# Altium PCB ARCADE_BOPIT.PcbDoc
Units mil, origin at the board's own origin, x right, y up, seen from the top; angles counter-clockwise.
Board outline 5835 x 3835 mil, 2 copper layers (Top Layer, Bottom Layer); 35 components, 24 nets, 112 pads, 0 vias.
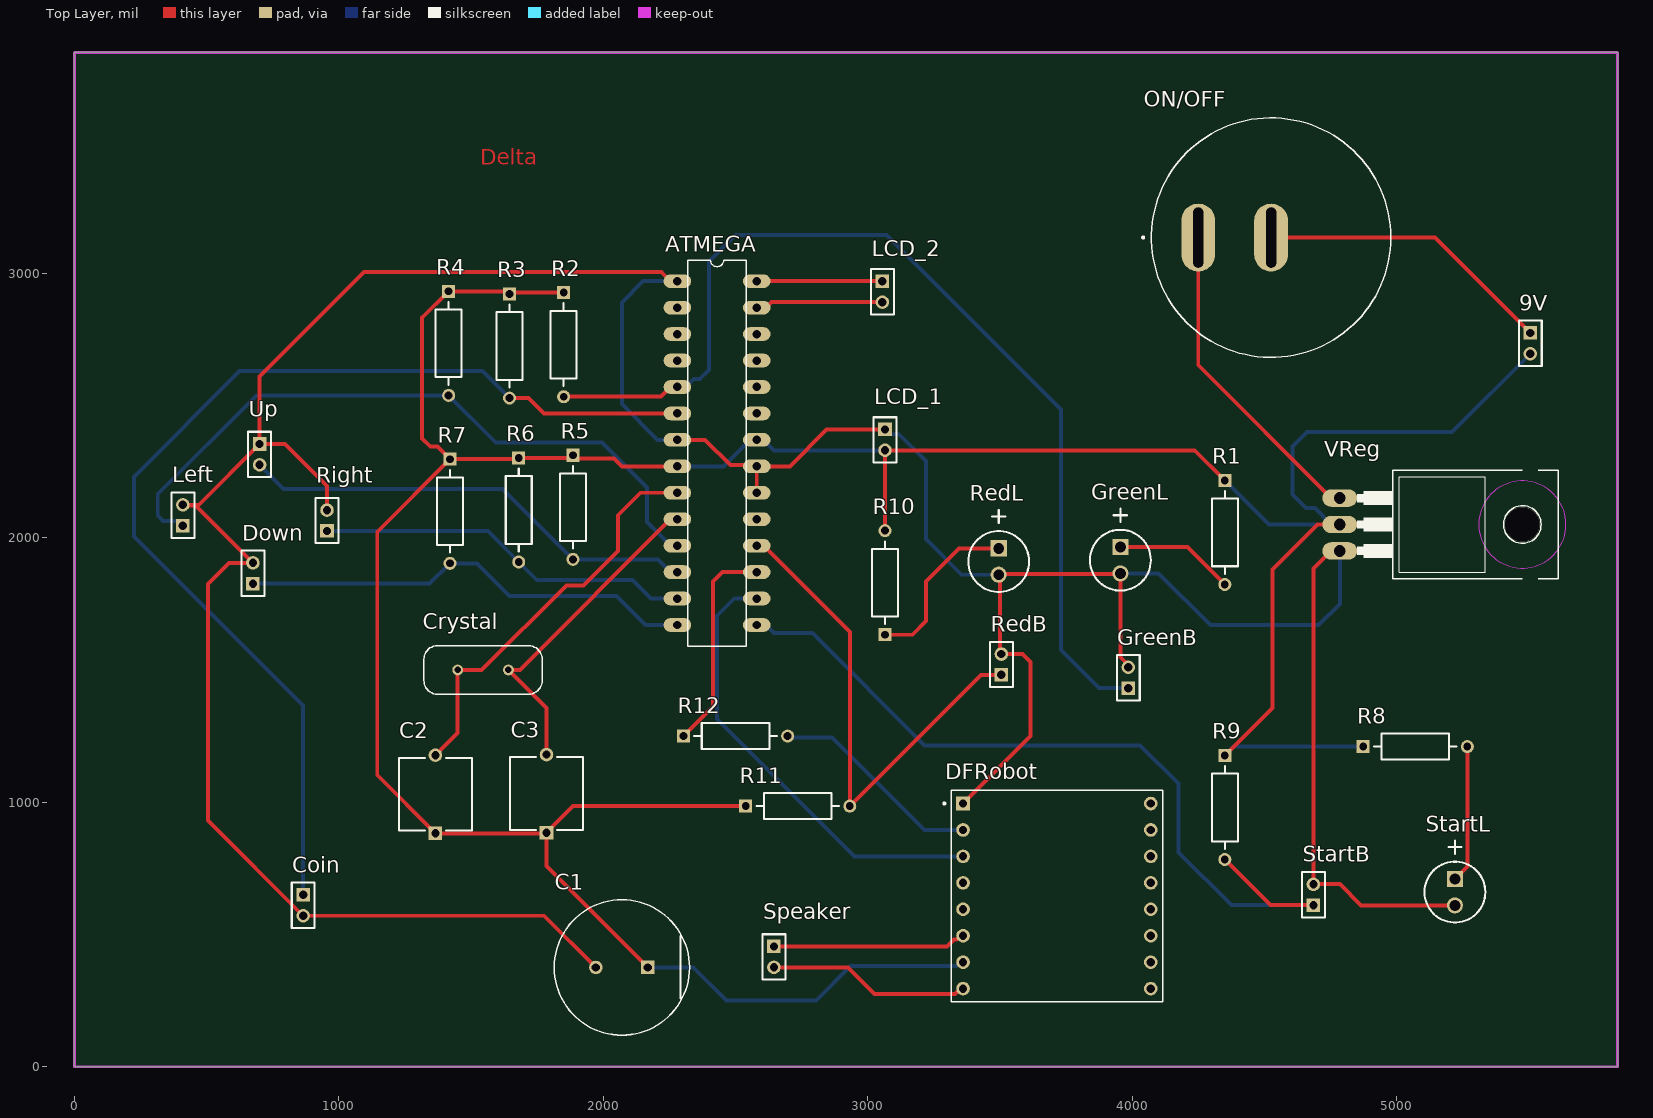
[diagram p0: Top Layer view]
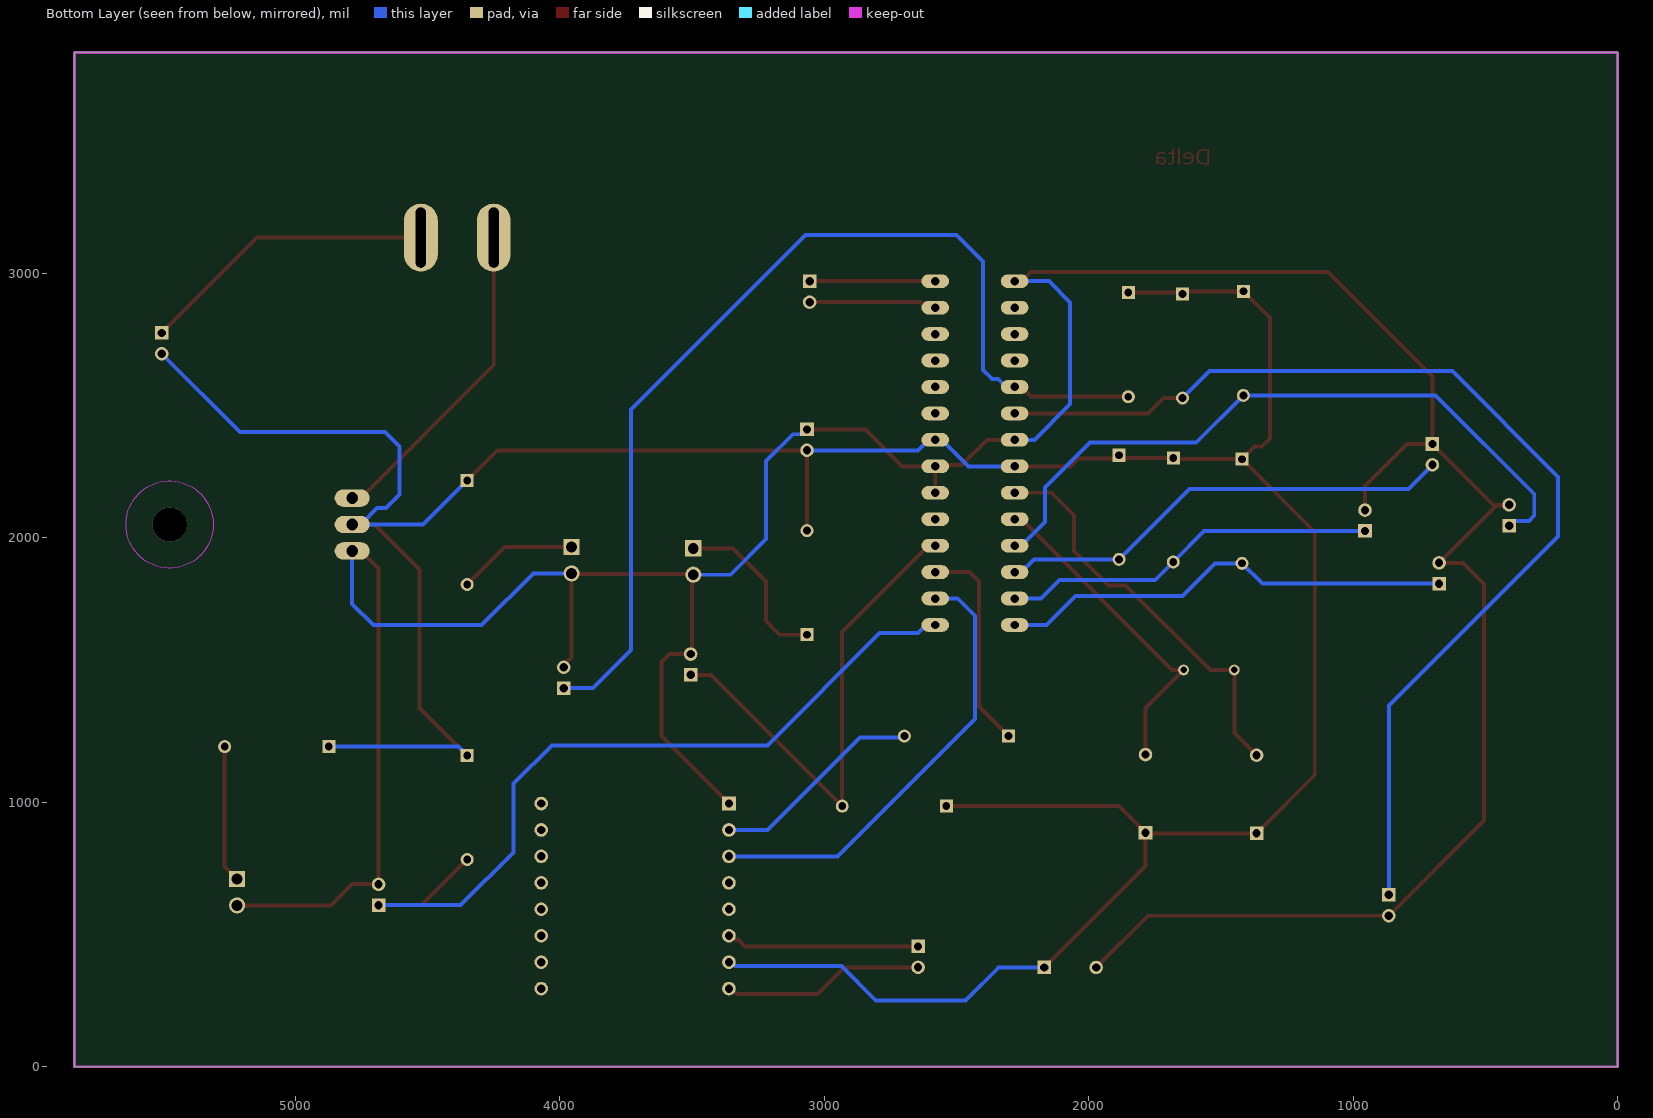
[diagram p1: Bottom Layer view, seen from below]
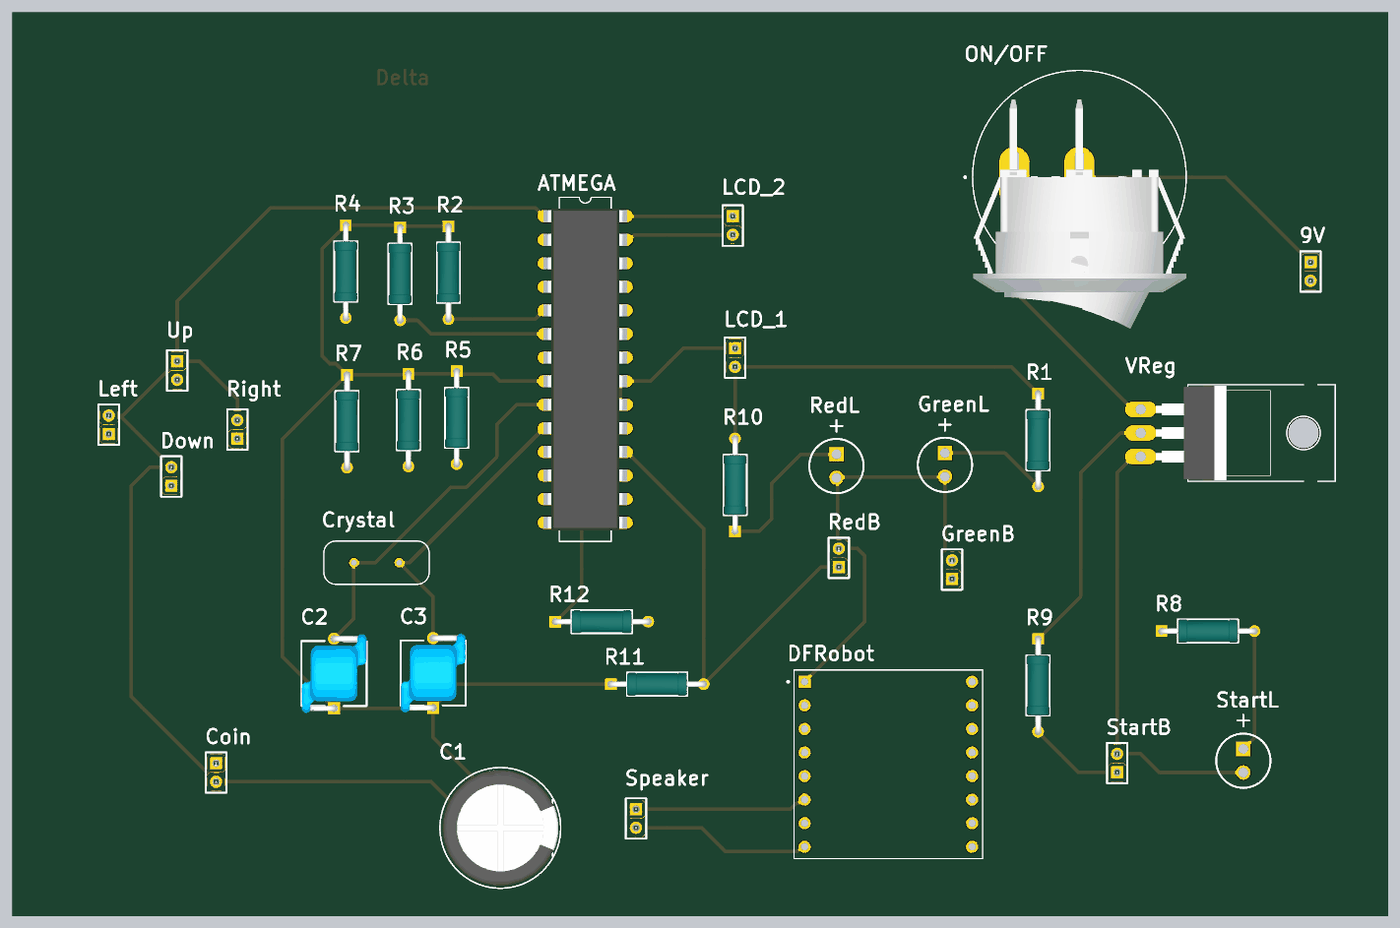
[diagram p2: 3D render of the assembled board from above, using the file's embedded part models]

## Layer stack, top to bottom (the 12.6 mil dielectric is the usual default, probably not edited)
Top Solder: solder mask 0.4, Solder Resist, Dk 3.5
Top Layer: signal copper 1.4
Dielectric 1: dielectric 12.6, FR-4, Dk 4.8
Bottom Layer: signal copper 1.4
Bottom Solder: solder mask 0.4, Solder Resist, Dk 3.5

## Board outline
0,0 5835,0 5835,3835 0,3835

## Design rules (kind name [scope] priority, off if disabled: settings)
BoardOutlineClearance [All] p1: gap=7.87 ignorepadtopadclearanceinfootprint=FALSE except(15.75: Arc-SplitBarrior Arc-SplitContinuation Track-SplitBarrior Track-SplitContinuation SMDPad-SplitBarrior SMDPad-SplitContinuation THPad-SplitBarrior THPad-SplitContinuation Via-SplitBarrior Via-SplitContinuation Fill-SplitBarrior Fill-SplitContinuation Poly-SplitBarrior Poly-SplitContinuation Region-SplitBarrior Region-SplitContinuation Text-SplitBarrior Text-SplitContinuation)
Clearance "Clearance Bottom Layer" [OnLayer('Bottom Layer')] p1: gap=8 ignorepadtopadclearanceinfootprint=TRUE except(10: Arc-Text Track-Text SMDPad-Text THPad-Text Via-Text Fill-Text Poly-Text Region-Text Text-Text)
Clearance "Clearance Top Layer" [OnLayer('Top Layer')] p2: gap=8 ignorepadtopadclearanceinfootprint=TRUE except(10: Arc-Text Track-Text SMDPad-Text THPad-Text Via-Text Fill-Text Poly-Text Region-Text Text-Text)
Clearance [All] p3: gap=7.87 ignorepadtopadclearanceinfootprint=FALSE except(3.5: Arc-Arc Arc-Track Arc-SMDPad Track-Track Track-SMDPad SMDPad-SMDPad; 5: Arc-Via Track-Via SMDPad-Via THPad-Via Via-Via; 10: Arc-Text Track-Text SMDPad-Text THPad-Text Via-Text Fill-Text Poly-Text Region-Text Text-Text)
HoleSize [All] p1: absolutevalues=TRUE maxlimit=248.03 minlimit=7.87 maxpercent=80.000 minpercent=20.000
MinimumAnnularRing [All] p1: minimumring=3
MinimumSolderMaskSliver [All] p1: minsoldermaskwidth=3.94
PolygonConnect PolygonConnect_1 [All] p1: thpad.connectstyle=Relief thpad.reliefconductorwidth=20 thpad.reliefentries=4 thpad.polygonreliefangle="90 Angle" thpad.airgapwidth=10 smdpad.connectstyle=Relief smdpad.reliefconductorwidth=20 smdpad.reliefentries=4 smdpad.polygonreliefangle="90 Angle" smdpad.airgapwidth=10 via.connectstyle=Direct via.reliefconductorwidth=20 via.reliefentries=4 via.polygonreliefangle="90 Angle" via.airgapwidth=10
RoutingCorners [All] p1: cornerstyle=Round minsetback=100 maxsetback=100
RoutingVias [All] p1: holewidth=19.68 width=39.37 viastyle="Through Hole" minholewidth=7.87 minwidth=17.72 maxholewidth=39.37 maxwidth=78.74
SilkToSilkClearance [All] p1: silktosilkclearance=3.94
SilkToSolderMaskClearance [IsPad] p1: minsilkscreentomaskgap=3.94 clearancetoexposedcopper=TRUE
SolderMaskExpansion [All] p1: expansion=4 istentingtop=FALSE
Width [All] p1: maxlimit=100 minlimit=3.5 preferedwidth=15
25 further rules are at their usual default settings.

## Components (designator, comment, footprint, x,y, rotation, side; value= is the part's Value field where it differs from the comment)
9V "9V" FP-M22-2510205-MFG 5505,2735 r270 top
ATMEGA "ATMEGA328P-PN" DIL28 2430,2320 r0 top
C1 "0.33uF" FP-RAD-TH-D_12_5_0_5-L_20-MFG 2070,375 r180 top
C2 "22pF" FP-DE6_D7_T7_F7_5_d0_6-0-MFG 1365,1030 r90 top
C3 "22pF" FP-DE6_D7_T7_F7_5_d0_6-0-MFG 1785,1032.36 r90 top
Coin "Coin" FP-M22-2510205-MFG 865,610 r270 top
Crystal "Crystal" XTAL_ECS-160-20-4X 1545,1500 r180 top
DFRobot "DFR0299" MODULE_DFR0299 3715,645 r0 top
Down "Down" FP-M22-2510205-MFG 675,1865.63 r90 top
GreenB "Green Button" FP-M22-2510205-MFG 3985,1470.63 r90 top
GreenL "GreenLED" AVAG-HLMP-3301-2 3955,1965 r270 top
LCD_1 "LCD_1" FP-M22-2510205-MFG 3065,2370 r270 top
LCD_2 "LCD_2" FP-M22-2510205-MFG 3055,2930 r270 top
Left "Left" FP-M22-2510205-MFG 410,2085 r90 top
ON/OFF "On/Off Switch" E-SWITCH_RR511D1121 4525,3135 r0 top
R1 "1k" FP-MRS25-MFG 4350,2020 r270 top
R2 "1k" FP-MRS25-MFG 1850,2730 r270 top
R3 "1k" FP-MRS25-MFG 1645,2725 r270 top
R4 "1k" FP-MRS25-MFG 1415,2735 r270 top
R5 "1k" FP-MRS25-MFG 1885,2115 r270 top
R6 "1k" FP-MRS25-MFG 1680,2105 r270 top
R7 "1k" FP-MRS25-MFG 1420,2100 r270 top
R8 "1k" FP-MRS25-MFG 5070,1210 r0 top
R9 "1k" FP-MRS25-MFG 4350,980 r270 top
R10 "1k" FP-MRS25-MFG 3065,1830 r90 top
R11 "1k" FP-MRS25-MFG 2735,985 r0 top
R12 "1k" FP-MRS25-MFG 2500,1250 r0 top
RedB "RedB" FP-M22-2510205-MFG 3505,1520.63 r90 top
RedL "RedL" AVAG-HLMP-3301-2 3495,1960 r270 top
Right "Right" FP-M22-2510205-MFG 955,2065 r90 top
Speaker "Speaker" FP-M22-2510205-MFG 2645,415 r270 top
StartB "StartB" FP-M22-2510205-MFG 4685,650 r90 top
StartL "StartL" AVAG-HLMP-3301-2 5220,710 r270 top
Up "Up" FP-M22-2510205-MFG 700,2315 r270 top
VReg "Voltage Regulator" TO220 5035,2050 r270 top

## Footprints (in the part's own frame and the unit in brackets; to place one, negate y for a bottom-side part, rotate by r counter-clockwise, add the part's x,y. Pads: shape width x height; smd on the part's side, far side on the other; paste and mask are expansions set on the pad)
AVAG-HLMP-3301-2 [mm] "THD, 2-Leads, Body Dia 5.85mm"
  rect 1.55x1.55 hole 1.05: 1(0,0)
  round 1.55 hole 1.05: 2(2.54,0)
  silkscreen extent -3.68,-2.92 4.19,2.92
DIL28 [mil]
  oval 104x52 hole 32: 1(-150,650) 2(-150,550) 3(-150,450) 4(-150,350) 5(-150,250) 6(-150,150) 7(-150,50) 8(-150,-50) 9(-150,-150) 10(-150,-250) 11(-150,-350) 12(-150,-450) 13(-150,-550) 14(-150,-650) 15(150,-650) 16(150,-550) 17(150,-450) 18(150,-350) 19(150,-250) 20(150,-150) 21(150,-50) 22(150,50) 23(150,150) 24(150,250) 25(150,350) 26(150,450) 27(150,550) 28(150,650)
  silkscreen extent -110,-730 110,730, body extent -200,-682 200,682, height 180
E-SWITCH_RR511D1121 [mm]
  oval 3.26x6.52 hole 0.98 slot 5.78 at 90 deg: 1(-7,0) 2(0,0)
  silkscreen extent -12.4,-11.5 11.5,11.5, body extent -11.5,-16.33 11.5,8.4, height 11.5
FP-DE6_D7_T7_F7_5_d0_6-0-MFG [mm]
  rect 1.3x1.3 hole 0.8 paste-1000 mask+0: 1(-3.75,0)
  round 1.3 hole 0.8 paste-1000 mask+0: 2(3.75,0)
  silkscreen extent -3.5,-3.5 3.5,3.5, body extent -4.5,-3.6 4.5,3.6, height 0.25
FP-M22-2510205-MFG [mm]
  rect 1.3x1.3 hole 0.8 paste-1000 mask+0: 1(-1,0)
  round 1.3 hole 0.8 paste-1000 mask+0: 2(1,0)
  silkscreen extent -2.17,-1.1 2.17,1.1, body extent -2.27,-1.2 2.27,1.2, height 0.25
FP-MRS25-MFG [mm]
  rect 1.25x1.25 hole 0.75 paste-1000 mask+0: 1(-5,0)
  round 1.25 hole 0.75 paste-1000 mask+0: 2(5,0)
  silkscreen extent -3.98,-1.25 3.98,1.25, body extent -5.72,-1.35 5.72,1.35, height 0.25
FP-RAD-TH-D_12_5_0_5-L_20-MFG [mm]
  rect 1.3x1.3 hole 0.8 paste-1000 mask+0: 1(-2.5,0)
  round 1.3 hole 0.8 paste-1000 mask+0: 2(2.5,0)
  silkscreen extent -6.5,-6.5 6.5,6.5, body extent -6.6,-6.6 6.6,6.6, height 0.25
MODULE_DFR0299 [mil]
  rect 51.5x51.5 hole 31.5: 1(-355,350)
  round 51.5 hole 31.5: 2(-355,250) 3(-355,150) 4(-355,50) 5(-355,-50) 6(-355,-150) 7(-355,-250) 8(-355,-350) 9(355,-350) 10(355,-250) 11(355,-150) 12(355,-50) 13(355,50) 14(355,150) 15(355,250) 16(355,350)
  silkscreen extent -429,-400 400,400
TO220 [mil]
  oval 66x132 hole 44: 1(-100,-250) 2(0,-250) 3(100,-250)
  round 130 hole 130 unplated: ""(0,440)
  Keep-Out Layer circle w0: c0,440 r165
  Keep-Out Layer circle w0: c0,440 r165
  silkscreen extent -205,-185 205,575, body extent -200,-68 200,113, height 1155
XTAL_ECS-160-20-4X [mm]
  round 1.03 hole 0.63: 1(-2.44,0) 2(2.44,0)
  silkscreen extent -5.68,-2.33 5.68,2.33

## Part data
9V Coin Down GreenB LCD_1 LCD_2 Left RedB Right Speaker StartB Up: library part CMP-15831-000005-1, "CONN HEADER VERT 2POS 2MM", Current Rating=2A, Manufacturer=Harwin, Manufacturer Part Number=M22-2510205, Package=0, Temperature="-40°C to +105°C", Temperature Range High=+105°C, Temperature Range Low=-40°C
ATMEGA: "AVR AVRÂ® ATmega Microcontroller IC 8-Bit 20MHz 32KB (16K x 16) FLASH 28-PDIP", Package="PDIP-28 Microchip"
C1: library part CMP-05427-000342-1, "Aluminum Electrolytic Capacitors (Radial Lead Type) AEC-Q200 Qualified 2200uF ±20% 16V", Capacitance=2.2mF, Case/Package=Radial, Dielectric Material=Aluminium, Max Operating Temperature=105°C, Min Operating Temperature=-55°C, Package Quantity=200, Ripple Current=1.89A, Tolerance=20%, Voltage=16V
C2 C3: library part CMP-06035-062244-1, "CAP CER 1000PF 300VAC RADIAL", Capacitance=1nF, Case/Package=Radial, Max Operating Temperature=125°C, Min Operating Temperature=-25°C, Package Quantity=700, Ratings=AEC-Q200, Resistor Type=Ceramic, Tolerance=20%, Voltage Rating (AC)=300V
Crystal: library part ECS-160-S-4, "16MHz Â±30ppm Crystal Series 40 Ohms HC-49/US", Package="HC49/US ECS International"
DFRobot: "Dfplayer - a Mini Mp3 Player", Package=None
GreenL RedL StartL: library part CMP-2000-06411-1, "T-1 3/4 (5 mm) Diffused LED Lamp, 1.9 V, -40 to 100 degC, 2-Pin THD, RoHS, Bulk", Emitting Color=Red, Forward Current=25mA, Forward Voltage=2.4V, Manufacturer=Avago, Operating Temp Range=-40Cto100C, Operating Temperature Classification=Industrial, Package Description="2-Pin Through Hole LED, Dia 5.85 mm", Package Reference=HLMP-3301, Package Type=T-13/4, Power Dissipation=85W, Reverse Voltage=5V, Test Current (It)=10mA
ON/OFF: library part RR511D1121, "Rocker Switch, RR5 Series, SPST,OFF-ON,Blk Rocker,I/O Legend, 20A, 125VAC, QC", Package=None
R1 R2 R3 R4 R5 R6 R7 R8 R9 R10 R11 R12: library part CMP-02408-000051-1, "RES 1K OHM 0.6W 1% AXIAL", Case/Package=Axial, Max Operating Temperature=155°C, Max Power Dissipation=600mW, Min Operating Temperature=-55°C, Package Quantity=5000, Resistance=1kR, Resistance Tolerance=1%, Resistor Type="Metal Film", Temperature Coefficient=50ppm/°C, Voltage Rating=350V
VReg: library part LM7805, "Linear Voltage Regulator IC Positive Fixed 1 Output 1.5A DDPAK/TO-263-3", Package=None

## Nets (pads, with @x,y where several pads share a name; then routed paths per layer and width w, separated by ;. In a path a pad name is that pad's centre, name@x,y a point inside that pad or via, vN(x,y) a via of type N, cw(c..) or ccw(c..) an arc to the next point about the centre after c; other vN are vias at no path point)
GND: 9V.2 ATMEGA.8 ATMEGA.22 C1.1 C2.1 C3.1 DFRobot.7 LCD_1.2 R1.1 R2.1 R3.1 R4.1 R5.1 R6.1 R7.1 R8.1 R9.1 R10.2 R11.1 VReg.2 | length 12879.7
  Top Layer w15: R2.1 1650,2926.85 R3.1 1635,2931.85 R4.1 1315,2831.85 1315,2375 1345.52,2344.48 1372.37,2344.48 R7.1 ; C1.1 1785,758.43 C3.1 ; ATMEGA.8 2070,2270 2040,2300 1896.85,2300 R5.1 1875,2301.85 R6.1 1675,2296.85 R7.1 ; R11.1 1885.28,985 C3.1 ; R10.2 LCD_1.2 4236.22,2330.63 R1.1 ; R9.1 4530,1356.85 4530,1880 4700,2050 VReg.2 ; R7.1 1145,2021.85 1145,1102.36 C2.1 1782.64,882.36 C3.1
  Bottom Layer w15: C1.1 2340,375 2460.01,254.99 2465,250 2805,250 2935,380 3335,380 ; ATMEGA.8 2454,2270 2554,2370 ATMEGA.22 2606,2370 2645.37,2330.63 LCD_1.2 ; R9.1 4383.15,1210 R8.1 ; R1.1 4516.85,2050 VReg.2@4752,2050 ; VReg.2 VReg.2@4752,2050 ; 9V.2 5209.37,2400 4660,2400 4605,2345 4605,2163.79 4657.01,2111.77 4690.23,2111.77 VReg.2@4752,2050
Net9V_1: 9V.1 ON/OFF.2 | length 1129.4
  Top Layer w15: ON/OFF.2 5144.37,3135 9V.1
NetATMEGA_5: ATMEGA.5 GreenB.1 R2.2 | length 3871.5
  Top Layer w15: R2.2 2217.15,2533.15 2254,2570 ATMEGA.5
  Bottom Layer w15: ATMEGA.5 2312.51,2570 2343.55,2601.04 2366.04,2601.04 2400,2635 2400,3045 2500,3145 3070,3145 3730,2485 3730,1575 3873.74,1431.26 GreenB.1
NetATMEGA_6: ATMEGA.6 Coin.1 R3.2 | length 4132.7
  Top Layer w15: R3.2 1716.85,2528.15 1775,2470 ATMEGA.6
  Bottom Layer w15: Coin.1 865,1365 225,2005 225,2230 625,2630 1543.15,2630 R3.2
NetATMEGA_9: ATMEGA.9 C2.2 Crystal.2 | length 1554.8
  Top Layer w15: C2.2 1448.94,1261.57 Crystal.2 1540,1500 1860,1820 1925,1820 2055,1950 2055,2085 2140,2170 ATMEGA.9 ATMEGA.9@2272.92,2162.92
NetATMEGA_10: ATMEGA.10 C3.2 Crystal.1 | length 1254.7
  Top Layer w15: C3.2 1785,1356.06 Crystal.1 1684,1500 2254,2070 ATMEGA.10
NetATMEGA_11: ATMEGA.11 Left.1 R4.2 | length 2623.7
  Bottom Layer w15: Left.1 391.91,2063.72 335.07,2063.72 315,2083.79 315,2165 688.15,2538.15 R4.2 1593.15,2360 1995,2360 2165,2190 2165,2059 2254,1970 ATMEGA.11
NetATMEGA_12: ATMEGA.12 R5.2 Up.2 | length 1748
  Bottom Layer w15: Up.2 790.63,2185 1618.15,2185 R5.2 2205.85,1918.15 2254,1870 ATMEGA.12
NetATMEGA_13: ATMEGA.13 R6.2 Right.1 | length 1430.9
  Bottom Layer w15: Right.1 955.63,2025 1563.15,2025 R6.2 1748.15,1840 2110,1840 2180,1770 ATMEGA.13
NetATMEGA_14: ATMEGA.14 Down.1 R7.2 | length 1733.4
  Bottom Layer w15: Down.1 1343.11,1826.26 R7.2 1521.85,1903.15 1645,1780 2050,1780 2160,1670 ATMEGA.14
NetATMEGA_15: ATMEGA.15 R9.2 StartB.1 | length 3104.4
  Top Layer w15: R9.2 4350,780 4355,775 4358.15,775 4522.52,610.63 StartB.1
  Bottom Layer w15: ATMEGA.15 2614.59,1670 2644.59,1640 2790,1640 3215,1215 4030,1215 4175,1070 4175,810 4374.37,610.63 StartB.1
NetATMEGA_16: ATMEGA.16 DFRobot.3 | length 1712.3
  Bottom Layer w15: ATMEGA.16 2495,1770 2430,1705 2430,1315 2950,795 DFRobot.3
NetATMEGA_17: ATMEGA.17 R12.1 | length 810.8
  Top Layer w15: R12.1 2415,1361.85 2415,1835 2450,1870 ATMEGA.17
NetATMEGA_18: ATMEGA.18 R11.2 RedB.1 | length 1924.7
  Top Layer w15: ATMEGA.18 2606,1970 2931.85,1644.15 R11.2 3428.11,1481.26 RedB.1
NetATMEGA_27: ATMEGA.27 LCD_2.2 | length 483.5
  Top Layer w15: ATMEGA.27 2616.01,2870 2636.64,2890.63 LCD_2.2
NetATMEGA_28: ATMEGA.28 LCD_2.1 | length 475.3
  Top Layer w15: ATMEGA.28 3054.37,2970 LCD_2.1
NetDFRobot_2: DFRobot.2 R12.2 | length 810.2
  Bottom Layer w15: R12.2 2701.85,1245 2865,1245 3215,895 DFRobot.2
NetDFRobot_6: DFRobot.6 Speaker.1 | length 700.6
  Top Layer w15: Speaker.1 3299.49,454.37 3325.12,480 3335,480
NetDFRobot_8: DFRobot.8 Speaker.2 | length 733.8
  Top Layer w15: Speaker.2 2924.37,375.63 3025,275 3330,275 3335,280
NetGreenL_1: GreenL.1 R1.2 | length 453.8
  Top Layer w15: GreenL.1 4208.15,1965 R1.2
NetON/OFF_1: ON/OFF.1 VReg.1 | length 1226.2
  Top Layer w15: ON/OFF.1 4249.41,2652.59 4752,2150 VReg.1
NetR8_2: R8.2 StartL.1 | length 519.4
  Top Layer w15: StartL.1 5266.85,756.85 R8.2
NetR10_1: R10.1 RedL.1 | length 653.3
  Top Layer w15: R10.1 3168.15,1633.15 3220,1685 3220,1835 3345,1960 RedL.1
VCC: ATMEGA.1 ATMEGA.7 ATMEGA.20 ATMEGA.21 C1.2 Coin.2 DFRobot.1 Down.2 GreenB.2 GreenL.2 LCD_1.1 Left.2 RedB.2 RedL.2 Right.2 StartB.2 StartL.2 Up.1 VReg.3 | length 13599.7
  Top Layer w15: Right.2 955,2195 795.63,2354.37 Up.1 ; C1.2 1775.94,570.63 Coin.2 505,930.63 505,1825 585,1905 Down.2 458.09,2121.91 412.46,2121.91 Left.2 470,2124.37 Up.1 ; ATMEGA.7 2385,2370 2480,2275 2575,2275 ATMEGA.21 ; ATMEGA.1 2254,2970 2219,3005 1095,3005 700,2610 Up.1 ; ATMEGA.20 ATMEGA.21 ; LCD_1.1 2844.37,2409.37 2705,2270 ATMEGA.21 ; DFRobot.1 3615,1250 3615,1530 3585,1560 RedB.2 3500,1565 3500,1855 RedL.2 3497.5,1862.5 3952.5,1862.5 GreenL.2 3955,1548.01 3985,1518.01 GreenB.2 ; VReg.3 4752,1950 4685,1883 StartB.2 4685.63,690 4785,690 4865,610 StartL.2
  Bottom Layer w15: ATMEGA.7 2205,2370 2070,2505 2070,2890 2150,2970 ATMEGA.1 ; LCD_1.1 3083.09,2391.28 3118.72,2391.28 3220,2290 3220,1995 3355,1860 RedL.2 ; GreenL.2 4100,1865 4295,1670 4705,1670 4785,1750 VReg.3
pads on no net: ATMEGA.2 ATMEGA.3 ATMEGA.4 ATMEGA.19 ATMEGA.23 ATMEGA.24 ATMEGA.25 ATMEGA.26 DFRobot.4 DFRobot.5 DFRobot.9 DFRobot.10 DFRobot.11 DFRobot.12 DFRobot.13 DFRobot.14 DFRobot.15 DFRobot.16 VReg.

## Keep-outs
Keep-Out Layer:
  the board outline again, w10

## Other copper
Top Layer:
  text "Delta" at 1535,3410 h60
